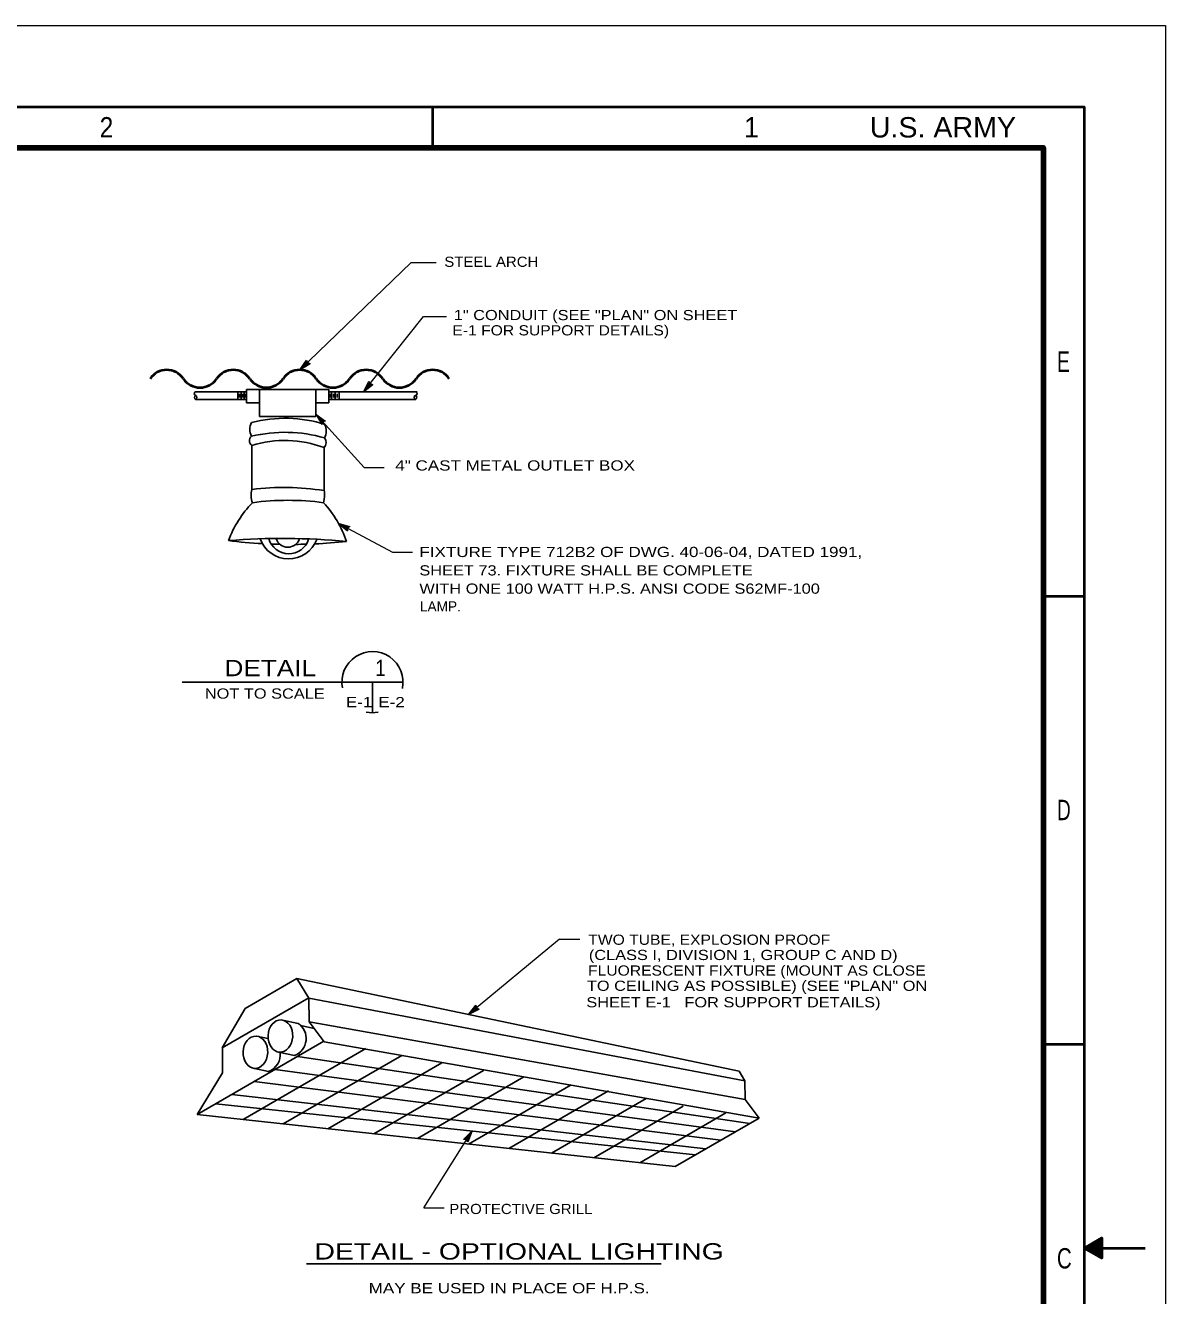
# Model space of a CAD drawing. Extents: x -39.6 to 16.1, y -17.6 to 34.
# Drawn here: x 2.11 to 16.1, y -3.17 to 12.41 of the extents above; entities that cross this region are included whole.
import ezdxf
from ezdxf.enums import TextEntityAlignment as Align

# ---------------------------------------------------------------- set-up
doc = ezdxf.new("R2010")
doc.units = 0
doc.header["$LTSCALE"] = 0.05
doc.layers.add('1', color=7, linetype='Continuous', lineweight=13)

msp = doc.modelspace()

# ---------------------------------------------------------------- linework, layer by layer
at = {"layer": '1', "lineweight": 40}
for p, q in [((7.10179, 11.40842), (7.10179, 10.90842)), ((14.60179, 5.40842), (15.10179, 5.40842)), ((14.60179, -0.09158), (15.10179, -0.09158)), ((15.10179, -2.59158), (15.85179, -2.59158))]:
    msp.add_line(p, q, dxfattribs=at)
at = {"layer": '1'}
for p, q in [((5.47679, 8.18142), (6.84379, 9.49942)), ((6.84379, 9.49942), (7.15079, 9.49942)), ((6.25579, 7.91142), (6.99279, 8.83742)), ((6.99279, 8.83742), (7.27479, 8.83742)), ((5.47679, 8.18142), (5.55879, 8.30342)), ((5.47679, 8.18142), (5.60179, 8.25942)), ((5.50379, 8.20742), (5.55679, 8.28642)), ((5.52979, 8.23242), (5.55479, 8.27042)), ((5.55479, 8.27042), (5.55879, 8.26042)), ((5.55679, 8.28642), (5.56479, 8.26642)), ((5.55879, 8.26042), (5.56779, 8.25642)), ((5.56479, 8.26642), (5.58479, 8.25842)), ((5.50379, 8.20742), (5.58479, 8.25842)), ((5.52979, 8.23242), (5.56779, 8.25642)), ((6.25579, 7.91142), (6.32079, 8.04342)), ((6.25579, 7.91142), (6.36979, 8.00442)), ((6.27879, 7.94042), (6.32179, 8.02642)), ((6.27879, 7.94042), (6.35279, 8.00142)), ((6.30079, 7.96842), (6.32179, 8.01042)), ((6.30079, 7.96842), (6.33679, 7.99842)), ((6.32179, 8.02642), (6.33179, 8.00642)), ((6.32179, 8.01042), (6.32679, 8.00042)), ((6.32679, 8.00042), (6.33679, 7.99842)), ((6.33179, 8.00642), (6.35279, 8.00142)), ((5.67079, 7.63942), (6.26579, 6.98542)), ((5.67079, 7.63942), (5.79079, 7.55342)), ((5.67079, 7.63942), (5.74479, 7.51242)), ((5.69579, 7.61242), (5.77379, 7.55642)), ((5.69579, 7.61242), (5.74379, 7.52942)), ((5.71979, 7.58542), (5.74379, 7.54642)), ((5.71979, 7.58542), (5.75779, 7.55842)), ((5.74779, 7.55542), (5.74379, 7.54642)), ((5.75279, 7.54942), (5.74379, 7.52942)), ((5.75779, 7.55842), (5.74779, 7.55542)), ((5.77379, 7.55642), (5.75279, 7.54942)), ((6.26579, 6.98542), (6.51179, 6.98542)), ((5.94679, 6.30342), (6.61279, 5.94542)), ((5.94679, 6.30342), (6.08879, 6.26242)), ((5.94679, 6.30342), (6.05879, 6.20842)), ((5.97979, 6.28542), (6.07179, 6.25942)), ((5.97979, 6.28542), (6.05279, 6.22342)), ((6.01079, 6.26842), (6.04679, 6.23942)), ((6.01079, 6.26842), (6.05579, 6.25642)), ((6.05579, 6.25642), (6.04679, 6.24942)), ((6.04679, 6.24942), (6.04679, 6.23942)), ((6.05379, 6.24542), (6.05279, 6.22342)), ((6.07179, 6.25942), (6.05379, 6.24542)), ((6.61279, 5.94542), (6.85779, 5.94542)), ((8.66279, 1.19842), (7.54379, 0.27342)), ((8.66279, 1.19842), (8.91279, 1.19842)), ((7.54379, 0.27342), (7.63479, 0.38942)), ((7.54379, 0.27342), (7.67479, 0.34142)), ((7.57279, 0.29742), (7.63179, 0.37242)), ((7.57279, 0.29742), (7.65779, 0.34142)), ((7.59979, 0.32042), (7.62879, 0.35642)), ((7.59979, 0.32042), (7.64079, 0.34142)), ((7.62879, 0.35642), (7.63179, 0.34642)), ((7.63179, 0.37242), (7.63779, 0.35142)), ((7.63179, 0.34642), (7.64079, 0.34142)), ((7.63779, 0.35142), (7.65779, 0.34142)), ((6.99779, -2.09758), (7.58879, -1.15458)), ((7.58879, -1.15458), (7.48579, -1.26058)), ((7.56879, -1.18558), (7.50179, -1.25458)), ((7.54979, -1.21658), (7.51879, -1.24958)), ((7.54979, -1.21658), (7.53479, -1.25958)), ((7.56879, -1.18558), (7.53579, -1.27658)), ((7.58879, -1.15458), (7.53879, -1.29258)), ((7.52379, -1.25758), (7.50179, -1.25458)), ((7.52779, -1.25158), (7.51879, -1.24958)), ((7.53579, -1.27658), (7.52379, -1.25758)), ((7.53479, -1.25958), (7.52779, -1.25158)), ((6.99779, -2.09758), (7.24779, -2.09758))]:
    msp.add_line(p, q, dxfattribs=at)
at = {"layer": '1', "lineweight": 25}
for p, q in [((4.19679, 7.91142), (4.81579, 7.91142)), ((4.19679, 7.82042), (4.81579, 7.82042)), ((4.71379, 7.82042), (4.71379, 7.91142)), ((4.73479, 7.84542), (4.73479, 7.88742)), ((4.75379, 7.82042), (4.75379, 7.91142)), ((4.77479, 7.84542), (4.77479, 7.88742)), ((4.79179, 7.82042), (4.79179, 7.91142)), ((4.80579, 7.84542), (4.80579, 7.88742)), ((4.81979, 7.77942), (4.81979, 7.94042)), ((4.81979, 7.94042), (5.82979, 7.94042)), ((4.98179, 7.94042), (4.98179, 7.61242)), ((5.67079, 7.94042), (5.67079, 7.61242)), ((5.82579, 7.91142), (6.91379, 7.91142)), ((5.82579, 7.82042), (6.89779, 7.82042)), ((5.82979, 7.77942), (5.82979, 7.94042)), ((5.84579, 7.84542), (5.84579, 7.88742)), ((5.86279, 7.82042), (5.86279, 7.91142)), ((5.88779, 7.84542), (5.88779, 7.88742)), ((5.91079, 7.82042), (5.91079, 7.91142)), ((5.93379, 7.84542), (5.93379, 7.88742)), ((5.95979, 7.82042), (5.95979, 7.91142)), ((4.81979, 7.77942), (4.98079, 7.77942)), ((5.67179, 7.77942), (5.82979, 7.77942)), ((4.98179, 7.61242), (5.67079, 7.61242)), ((4.88679, 7.25542), (4.88679, 6.71642)), ((5.77279, 7.22842), (5.77279, 6.71342)), ((4.03279, 4.35142), (6.74179, 4.35142)), ((6.36679, 4.35142), (6.36679, 3.97642)), ((4.80279, 0.34742), (5.43679, 0.71442)), ((5.43679, 0.71442), (5.58679, 0.47642)), ((5.43679, 0.71442), (10.86579, -0.42158)), ((4.52079, -0.13558), (5.58479, 0.47942)), ((5.58679, 0.47642), (10.93879, -0.53758)), ((4.52079, -0.13558), (4.80279, 0.34742)), ((5.26179, 0.20542), (5.45379, 0.16542)), ((5.58979, 0.18242), (10.94079, -0.76958)), ((4.94579, 0.00842), (5.08379, -0.02058)), ((5.48479, 0.13942), (5.65279, 0.10442)), ((4.21679, -0.95158), (5.76879, -0.05458)), ((4.52479, -0.44158), (4.52479, -0.13558)), ((4.78079, -1.01358), (6.28479, -0.14458)), ((5.77379, -0.06158), (11.11179, -0.99658)), ((5.21479, -0.18658), (5.41079, -0.22758)), ((5.27279, -1.06658), (6.72579, -0.22658)), ((5.44579, -0.20858), (5.48579, -0.21658)), ((5.44779, -0.23958), (10.99979, -1.06158)), ((4.21679, -0.95158), (4.52479, -0.44158)), ((4.89979, -0.38358), (5.09179, -0.42358)), ((5.13479, -0.40158), (5.15979, -0.40658)), ((5.17279, -0.39958), (10.82079, -1.16458)), ((5.81979, -1.12658), (7.21679, -0.31858)), ((6.38379, -1.18858), (7.73079, -0.41058)), ((10.86579, -0.42158), (10.93879, -0.53758)), ((4.91379, -0.54858), (10.64079, -1.26858)), ((6.91779, -1.24658), (8.22579, -0.49058)), ((7.54479, -1.31458), (8.80479, -0.58658)), ((4.64079, -0.70658), (10.45779, -1.37458)), ((8.04079, -1.36858), (9.26379, -0.66158)), ((8.56479, -1.42558), (9.72579, -0.75458)), ((4.44379, -0.82058), (10.33279, -1.44658)), ((9.08379, -1.48258), (10.17879, -0.84958)), ((9.64979, -1.54458), (10.70579, -0.93358)), ((5.55779, -2.78558), (9.90879, -2.78558))]:
    msp.add_line(p, q, dxfattribs=at)
at = {"layer": '1'}
for points in [[(-25.89821, 12.40842), (16.10179, 12.40842), (16.10179, -17.59158)], [(5.55879, 8.30342), (5.57079, 8.27142), (5.60179, 8.25942)], [(6.32079, 8.04342), (6.33679, 8.01342), (6.36979, 8.00442)], [(5.79079, 7.55342), (5.75779, 7.54342), (5.74479, 7.51242)], [(6.08879, 6.26242), (6.06179, 6.24142), (6.05879, 6.20842)], [(7.63479, 0.38942), (7.64379, 0.35642), (7.67479, 0.34142)], [(7.53879, -1.29258), (7.51979, -1.26458), (7.48579, -1.26058)]]:
    msp.add_lwpolyline(points, dxfattribs=at)
at = {"layer": '1', "lineweight": 40}
for points in [[(-24.89821, -16.59158), (-24.89821, 11.40842), (15.10179, 11.40842), (15.10179, -16.59158)], [(15.10179, -2.59158), (15.31879, -2.46658), (15.31879, -2.71658)]]:
    msp.add_lwpolyline(points, close=True, dxfattribs=at)
at = {"layer": '1', "lineweight": 90}
msp.add_lwpolyline([(-23.39821, 10.90842), (14.60179, 10.90842), (14.60179, -16.09158), (-23.39821, -16.09158)], close=True, dxfattribs=at)
at = {"layer": '1', "lineweight": 25}
for points in [[(5.58679, 0.47642), (5.58979, 0.18242), (5.77379, -0.06158)], [(10.93879, -0.53758), (10.94079, -0.76958), (11.11179, -0.99658)], [(4.21679, -0.95158), (10.08179, -1.59158), (11.11179, -0.99658)]]:
    msp.add_lwpolyline(points, dxfattribs=at)
at = {"layer": '1', "lineweight": 40}
for points in [[(15.14479, -2.59158), (15.29779, -2.50258), (15.29779, -2.68058), (15.14579, -2.59258)], [(15.18479, -2.59258), (15.27679, -2.53858), (15.27679, -2.64458), (15.18379, -2.59058)], [(15.22679, -2.59258), (15.25679, -2.57458), (15.25679, -2.60858), (15.22979, -2.59358)]]:
    msp.add_lwpolyline(points, dxfattribs=at)
for centre, start, end in [((3.84179, 7.93542), 34.0772, 145.92281), ((4.65779, 7.93542), 34.0772, 145.92281), ((5.47379, 7.93542), 34.0772, 145.92281), ((6.28979, 7.93542), 34.0772, 145.92281), ((7.10579, 7.93542), 34.0772, 145.92281), ((4.24979, 8.21142), 214.0772, 325.92281), ((5.06579, 8.21142), 214.0772, 325.92281), ((5.88179, 8.21142), 214.0772, 325.92281), ((6.69779, 8.21142), 214.0772, 325.92281)]:
    msp.add_arc(centre, 0.24629, start, end, dxfattribs=at)
at = {"layer": '1', "lineweight": 25}
for centre, radius, start, end in [((5.04939, 7.45042), 0.18793, 153.10794, 206.20997), ((5.29383, 5.97459), 1.6143, 72.29396, 104.78794), ((5.60175, 7.43428), 0.19811, 333.99319, 23.22937), ((4.92628, 7.31369), 0.07039, 130.25329, 235.87969), ((5.29276, 5.67054), 1.74617, 73.80475, 103.64636), ((5.70474, 7.29213), 0.09322, 316.8877, 36.37938), ((5.29026, 5.94466), 1.37145, 69.39999, 107.10902), ((5.16276, 6.64496), 0.28507, 165.48408, 198.73211), ((5.27745, 3.58448), 3.1562, 80.95224, 97.11009), ((5.318, 6.65036), 0.45915, 347.81103, 7.8938), ((5.92028, 5.57943), 1.41576, 136.53123, 158.97301), ((5.32979, 3.27597), 3.30645, 82.40524, 97.59476), ((4.74152, 5.62543), 1.38287, 19.03381, 42.14892), ((5.26286, -1.95011), 8.06491, 84.4076, 94.7231), ((5.37302, 12.57061), 6.52926, 263.18997, 266.8548), ((5.33757, 6.23435), 0.37108, 199.50946, 339.33973), ((5.33952, 6.1823), 0.2552, 195.65931, 343.17143), ((5.32809, 6.15548), 0.14906, 195.98959, 343.20909), ((5.37302, 12.57061), 6.52926, 267.8218, 268.77788), ((5.37302, 12.57061), 6.52926, 270.43672, 271.58669), ((5.37302, 12.57061), 6.52926, 272.49971, 275.94073), ((6.36679, 4.35142), 0.375, 348.02387, 190.92017), ((6.36679, 4.35142), 0.375, 257.81974, 280.71312), ((5.33234, -0.01995), 0.22161, 290.45652, 56.7671), ((5.01434, -0.21595), 0.22161, 290.45652, 6.91321)]:
    msp.add_arc(centre, radius, start, end, dxfattribs=at)
for centre, major_axis, ratio, start_param, end_param in [((4.19729, 7.88992), (0.0005, -0.0215), 0.815101, 3.14159265, 6.28318531), ((6.89729, 7.89092), (-0.0005, -0.0215), 0.8151, 6.28318531, 9.42477796)]:
    msp.add_ellipse(centre, major_axis=major_axis, ratio=ratio, start_param=start_param, end_param=end_param, dxfattribs=at)
for centre, major_axis, ratio in [((4.19679, 7.84442), (0, 0.024), 0.65341), ((6.89379, 7.84542), (0, 0.024), 0.65341), ((5.23679, 0.00992), (-0.01, -0.1975), 0.767986), ((4.92979, -0.18908), (-0.01, -0.1975), 0.767986)]:
    msp.add_ellipse(centre, major_axis=major_axis, ratio=ratio, dxfattribs=at)

# ---------------------------------------------------------------- texts
at = {"layer": '1'}
for s, height, width, p in [('2', 0.25, 0.9, (3.10229, 11.03342)), ('E', 0.25, 0.7, (14.84679, 8.15842)), ('DETAIL', 0.2, 1.2, (5.11279, 4.42442)), ('1', 0.2, 0.85, (6.46529, 4.42542)), ('E-1', 0.125, 1.25, (6.20279, 4.04442)), ('E-2', 0.125, 1.25, (6.60079, 4.04442)), ('D', 0.25, 0.7, (14.85279, 2.65842)), ('DETAIL - OPTIONAL LIGHTING', 0.2, 1.3, (8.16679, -2.73158)), ('C', 0.25, 0.75, (14.85879, -2.84158))]:
    msp.add_text(s, height=height, dxfattribs=dict(at, width=width)).set_placement(p, align=Align.CENTER)
msp.add_text('1', height=0.2503, dxfattribs=at).set_placement((11.01879, 11.03342), align=Align.CENTER)
for s, height, width, p in [('U.S. ARMY', 0.25, 1.05, (14.26579, 11.03342)), ('NOT TO SCALE', 0.125, 1.2, (5.78079, 4.14942))]:
    msp.add_text(s, height=height, dxfattribs=dict(at, width=width)).set_placement(p, align=Align.RIGHT)
for s, width, p in [('STEEL ARCH', 1.1, (7.24879, 9.44642)), ('1" CONDUIT (SEE "PLAN" ON SHEET', 1.2, (7.36479, 8.79242)), ('E-1 FOR SUPPORT DETAILS)', 1.15, (7.34779, 8.60542)), ('4" CAST METAL OUTLET BOX', 1.25, (6.64679, 6.94742)), ('FIXTURE TYPE 712B2 OF DWG. 40-06-04, DATED 1991,', 1.25, (6.94279, 5.88642)), ('SHEET 73. FIXTURE SHALL BE COMPLETE', 1.2, (6.94279, 5.66042)), ('WITH ONE 100 WATT H.P.S. ANSI CODE S62MF-100', 1.2, (6.94279, 5.43642)), ('TWO TUBE, EXPLOSION PROOF', 1.15, (9.01579, 1.12942)), ('(CLASS I, DIVISION 1, GROUP C AND D)', 1.2, (9.02279, 0.94242)), ('FLUORESCENT FIXTURE (MOUNT AS CLOSE', 1.15, (9.01279, 0.75142)), ('TO CEILING AS POSSIBLE) (SEE "PLAN" ON', 1.2, (8.99879, 0.56442)), ('SHEET E-1   FOR SUPPORT DETAILS)', 1.2, (8.99179, 0.36242)), ('PROTECTIVE GRILL', 1.1, (7.30979, -2.17358)), ('MAY BE USED IN PLACE OF H.P.S.', 1.25, (6.32079, -3.14558))]:
    msp.add_text(s, height=0.125, dxfattribs=dict(at, width=width)).set_placement(p)
msp.add_text('LAMP.', height=0.125, dxfattribs=at).set_placement((6.94979, 5.21842))

doc.saveas('drawing.dxf')
